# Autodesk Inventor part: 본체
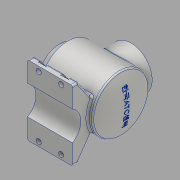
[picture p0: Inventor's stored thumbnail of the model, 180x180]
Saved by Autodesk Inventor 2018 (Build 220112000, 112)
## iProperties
Created: 2021-04
Part Number: 본체
Material: 알루미늄 6061
Document SubType Name: Modeling
Designer: home
Density: 2.7 g/cm^3
Appearance: 알루미늄 - 평지
Mass: 1641.94 g
Surface Area: 1038.73 cm^2
Volume: 608.127 cm^3
Author: home
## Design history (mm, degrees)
sketch "스케치2"
  geometry: L1 (-152.677, 0)-(152.677, 0); L2 (0, 27)-(0, 38); L3 (0, 38)-(12, 38); L4 (12, 38)-(12, 50); L5 (12, 50)-(108.336, 50); L6 (0, 27)-(22, 27); L7 (22, 27)-(22, 40); L8 (22, 40)-(101.916, 40); L9 (110, 0)-(120, 0); A1 r 113 centre (7, 0) between (120, 0) and (108.336, 50); A2 r 103 centre (7, 0) between (110, 0) and (101.916, 40); 2 further points
  constraints: 18 end point, 4 perpendicular, 4 point on circle, 3 horizontal, 2 centre point, 2 point on line, 1 coincident, 1 collinear, 1 midpoint, 1 vertical, 1 vertical alignment
  dimensions: "d7" = 12 distance of L2.end L3.end; "d9" = 100 diameter of L5 L1; "d11" = 76 diameter of L3 L1; "d12" = 54 diameter of L6 L1; "d14" = 108 distance from line of L4 L9.end; "d15" = 22 distance of L2.start L6.end; "d16" = 10 radial gap between concentric circles of A1 A2; "d17" = 113 radius of A1; "d21" = 80 diameter of L8 L1; "d113" = 130.67749 distance from line of L1.end L7
revolve "회전1" sketch "스케치2" stored, may be unused: angle "d25" = 90 deg
node "작업 평면1"
sketch "스케치4"
  geometry: L1 (-67, -62)-(-77, -62); L2 (-77, 62)-(-67, 62); L3 (-67, 62)-(-42.278, 26.694); L4 (-67, -62)-(-42.278, -26.694); L5 (-77, -62)-(-77, -25.981); L6 (-77, 25.981)-(-77, 62); C1 r 50 at (0, 0) reference; A1 r 50 centre (0, 0) between (-42.278, -26.694) and (-42.278, 26.694) reference; A2 r 30 centre (-92, 0) between (-77, -25.981) and (-77, 25.981); 2 further points
  constraints: 12 end point, 4 perpendicular, 4 point on circle, 1 centre point, 1 horizontal, 1 horizontal alignment
  dimensions: "d28" = 10 distance of L2.start L2.end; "d29" = 124 distance of L1.end L2.start; "d30" = 55 deg angle of L1 L4; "d31" = 55 deg angle of L2 L3; "d33" = 10 distance of L1.start L1.end; "d36" = 60 diameter of A2; "d37" = 15 distance of point (-77, 0) A2.centre; "d38" = 124 distance between parallel lines of L2 L1; "d39" = 19.32145 distance from line of A1.centre L3; "d40" = 19.32145 distance from line of A1.centre L4; "d41" = 28.85131 distance from line of L6.start L3; "d42" = 43.75326 distance from line of point (-77, 0) L3
extrude "돌출2" join sketch "스케치4" distance "d43" = 80; taper "d44" = 0 deg
sketch "스케치5"
  geometry: L1 (0, 36.019)-(0, 0) reference; L2 (0, 36.019)-(80, 36.019) reference; 3 further points
  dimensions: "d45" = 40 distance of point (60, 28.019) point (20, 28.019); "d46" = 20 distance from line of L1 point (20, 28.019); "d47" = 8 distance from line of L2 point (20, 28.019); "d48" = 8 distance from line of L2 point (60, 28.019)
hole "구멍1" sketch "스케치5" at (20, 28.019), (60, 28.019) diameter "d49" = 9; stored, may be unused: countersink angle "d53" = 90 deg, drill point angle "d55" = 0 deg; dims "d50" = 6, "d51" = 4, "d52" = 2, "d54" = 6
sketch "스케치6"
  geometry: L1 (-20, 8)-(60, 8) reference; L2 (7, 0)-(7, 8); L3 (7, 8)-(-7, 8); L4 (-7, 8)-(-7, 0); L5 (47, 0)-(47, 8); L6 (47, 8)-(33, 8); L7 (33, 8)-(33, 0); C1 r 4.5 at (40, 0) reference; A1 r 7 centre (0, 0) between (-7, 0) and (7, 0); A2 r 7 centre (40, 0) between (33, 0) and (47, 0); 3 further points
  constraints: 12 end point, 4 point on circle, 4 tangent, 3 coincident, 3 parallel, 2 centre point, 2 point on line, 1 horizontal, 1 vertical
  dimensions: "d56" = 8 distance from line of L1 point (0, 0); "d57" = 40 distance of point (40, 0) point (0, 0); "d58" = 14 diameter of A1; "d59" = 14 diameter of A2; "d60" = 90 deg angle of L5 L3
extrude "돌출3" cut sketch "스케치6" distance "d61" = 30; taper "d62" = 0 deg
node "작업 평면2"
sketch "스케치7"
  geometry: L1 (-20, -63.981)-(-20, 12.019) reference; C1 r 38 at (42, -25.981); 2 further points
  constraints: 1 centre point, 1 horizontal alignment, 1 midpoint
  dimensions: "d64" = 76 diameter of C1; "d66" = 62 distance from line of L1 C1.centre
extrude "돌출4" join sketch "스케치7" stored distance "d67" = 30; taper "d68" = 0 deg
hole "구멍2" diameter "d71" = 54; stored, may be unused: countersink angle "d75" = 90 deg, drill point angle "d77" = 0 deg; dims "d69" = 10, "d70" = 10, "d72" = 6, "d73" = 4, "d74" = 2, "d76" = 30
sketch "스케치8"
  geometry: C1 r 27 at (0, 0) reference; C2 r 38 at (0, 0) reference; 2 further points
  constraints: 1 horizontal alignment
  dimensions: "d78" = 32.5 distance of C1.centre point (32.5, 0)
hole "구멍3" sketch "스케치8" at (32.5, 0) diameter "d79" = 3.242; stored, may be unused: countersink angle "d83" = 90 deg, drill point angle "d85" = 118 deg; dims "d80" = 8, "d81" = 4, "d82" = 2, "d84" = 10
sketch "스케치9"
  geometry: 2 further points
  constraints: 1 vertical alignment
  dimensions: "d89" = 32.5 distance of point (0, 0) point (0, 32.5)
hole "구멍4" sketch "스케치9" at (0, 32.5) diameter "d90" = 3.242; stored, may be unused: countersink angle "d94" = 90 deg, drill point angle "d96" = 118 deg; dims "d91" = 8, "d92" = 4, "d93" = 2, "d95" = 10
fillet "모깎기1" dims "d103" = 3, "d109" = 3
fillet "모깎기2" dims "d104" = 3
fillet "모깎기3" dims "d105" = 3
chamfer "모따기1" distance "d106" = 1; stored, may be unused: second distance "d107" = 2, angle "d108" = 45 deg
node "작업 평면5"
sketch "스케치13"
  geometry: 2 further points
  constraints: 2 coincident, 1 other
feature "엠보싱1" sketch "스케치13" dims "d7" = 12, "d9" = 100, "d11" = 76, "d12" = 54, "d14" = 108, "d15" = 22, "d16" = 10, "d17" = 113, "d21" = 80, "d30" = 55 deg, "d111" = 0.5, "d112" = 0, "d113" = 130.67749
node "솔리드1"
mirror "미러1"
pattern_circular "원형 패턴2" dims angle "d98" = 360 deg
pattern_circular "원형 패턴3" dims angle "d101" = 360 deg
node "투영된 루프2"
node "투영된 루프3"
other parameters: "d32" = 77, "d34" = 40.49687, "d63" = -142
